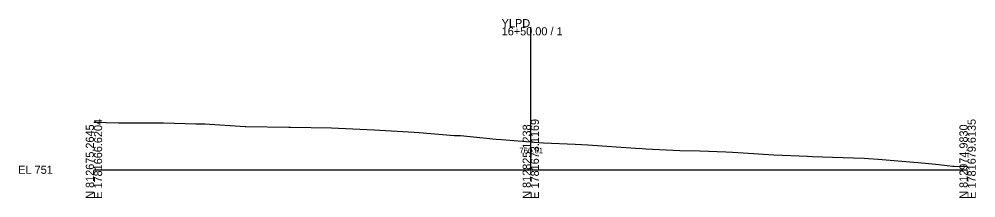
# Model space of a CAD drawing. Extents: x -26 to 353, y -10 to 9080.
# Drawn here: x -25.7 to 302.8, y 6490.3 to 6551.9 of the extents above; entities that cross this region are included whole.
import ezdxf

# ---------------------------------------------------------------- set-up
doc = ezdxf.new("R2010")
doc.units = 0
for name, color, linetype in [('Exist Cross Section Cell', 7, 'Continuous'), ('Exist XS Center Line Elevation Label', 7, 'Continuous'), ('Exist XS Ground Line', 7, 'Continuous')]:
    doc.layers.add(name, color=color, linetype=linetype)

msp = doc.modelspace()

# ---------------------------------------------------------------- linework, layer by layer
at = {"layer": 'Exist Cross Section Cell'}
for p, q in [((150, 6500), (150, 6549.05)), ((0, 6500), (150, 6500)), ((150, 6500), (300, 6500))]:
    msp.add_line(p, q, dxfattribs=at)
at = {"layer": 'Exist XS Ground Line'}
for p, q in [((0, 6516.35), (8.48, 6516.1)), ((8.48, 6516.1), (20.73, 6516.14)), ((20.73, 6516.14), (23.91, 6516.09)), ((23.91, 6516.09), (34.93, 6515.85)), ((34.93, 6515.85), (38.06, 6515.76)), ((38.06, 6515.76), (51.91, 6514.88)), ((51.91, 6514.88), (52.21, 6514.87)), ((52.21, 6514.87), (66.94, 6514.7)), ((66.94, 6514.7), (67.47, 6514.69)), ((67.47, 6514.69), (81.59, 6514.47)), ((81.59, 6514.47), (96.25, 6513.76)), ((96.25, 6513.76), (109.97, 6512.91)), ((109.97, 6512.91), (111.7, 6512.81)), ((111.7, 6512.81), (123.71, 6511.83)), ((123.71, 6511.83), (125.85, 6511.73)), ((125.85, 6511.73), (138.1, 6510.56)), ((138.1, 6510.56), (139.94, 6510.4)), ((139.94, 6510.4), (150, 6509.61)), ((150, 6509.61), (151.11, 6509.53)), ((151.11, 6509.53), (154.37, 6509.23)), ((154.37, 6509.23), (165.27, 6508.81)), ((165.27, 6508.81), (169.6, 6508.54)), ((169.6, 6508.54), (185.96, 6507.47)), ((185.96, 6507.47), (188.27, 6507.27)), ((188.27, 6507.27), (189.52, 6507.19)), ((189.52, 6507.19), (198.75, 6506.75)), ((198.75, 6506.75), (201.16, 6506.62)), ((201.16, 6506.62), (208.04, 6506.47)), ((208.04, 6506.47), (217.03, 6506.13)), ((217.03, 6506.13), (219.29, 6506.01)), ((219.29, 6506.01), (222.94, 6505.79)), ((222.94, 6505.79), (233.43, 6505.18)), ((233.43, 6505.18), (244.98, 6504.68)), ((244.98, 6504.68), (246.76, 6504.6)), ((246.76, 6504.6), (253.56, 6504.36)), ((253.56, 6504.36), (264.44, 6503.98)), ((264.44, 6503.98), (265.99, 6503.83)), ((265.99, 6503.83), (269.34, 6503.69)), ((269.34, 6503.69), (282.92, 6502.48)), ((282.92, 6502.48), (289.1, 6501.96)), ((289.1, 6501.96), (294.92, 6501.24)), ((294.92, 6501.24), (295.4, 6501.2)), ((295.4, 6501.2), (300, 6501.12))]:
    msp.add_line(p, q, dxfattribs=at)

# ---------------------------------------------------------------- texts
at = {"layer": 'Exist Cross Section Cell'}
for s, p in [('YLPD', (140, 6549.05)), ('16+50.00 / 1', (140, 6546.25)), ('EL 751', (-26, 6498.6))]:
    msp.add_text(s, height=2.8, dxfattribs=at).set_placement(p)
for s, p in [('N 812675.2645', (0, 6490)), ('E 1781666.6204', (2.8, 6490)), ('N 812825.1238', (150, 6490)), ('E 1781673.1169', (152.8, 6490)), ('N 812974.9830', (300, 6490)), ('E 1781679.6135', (302.8, 6490))]:
    msp.add_text(s, height=2.8, rotation=90, dxfattribs=at).set_placement(p)
at = {"layer": 'Exist XS Center Line Elevation Label'}
msp.add_text('760.61', height=2, dxfattribs=at).set_placement((146.08, 6505.61))

doc.saveas('drawing.dxf')
